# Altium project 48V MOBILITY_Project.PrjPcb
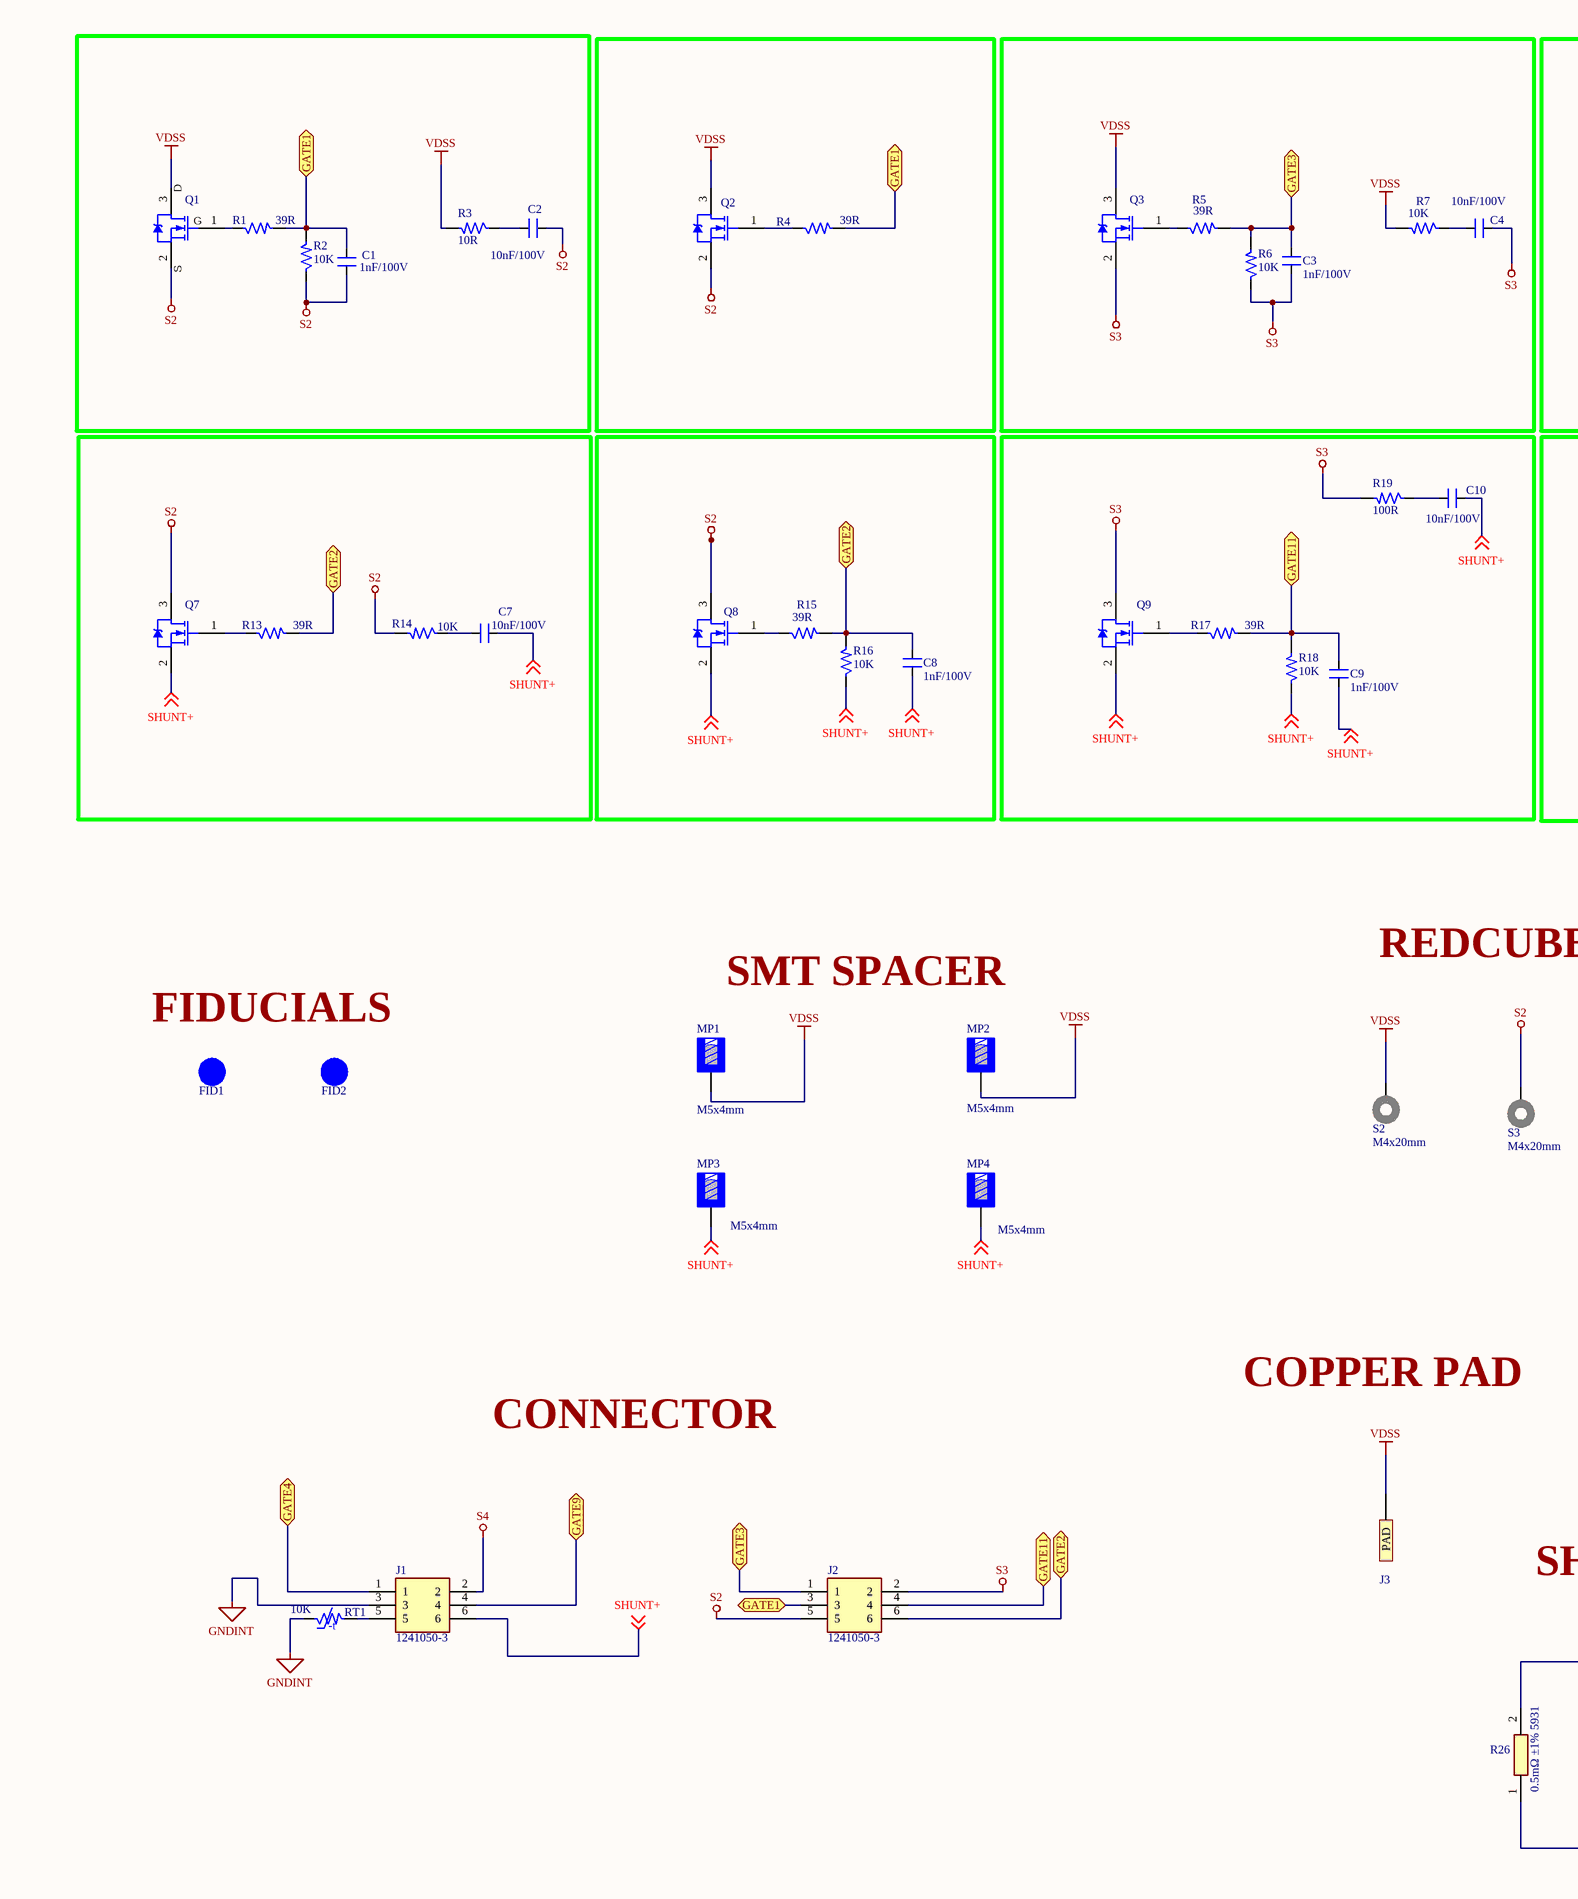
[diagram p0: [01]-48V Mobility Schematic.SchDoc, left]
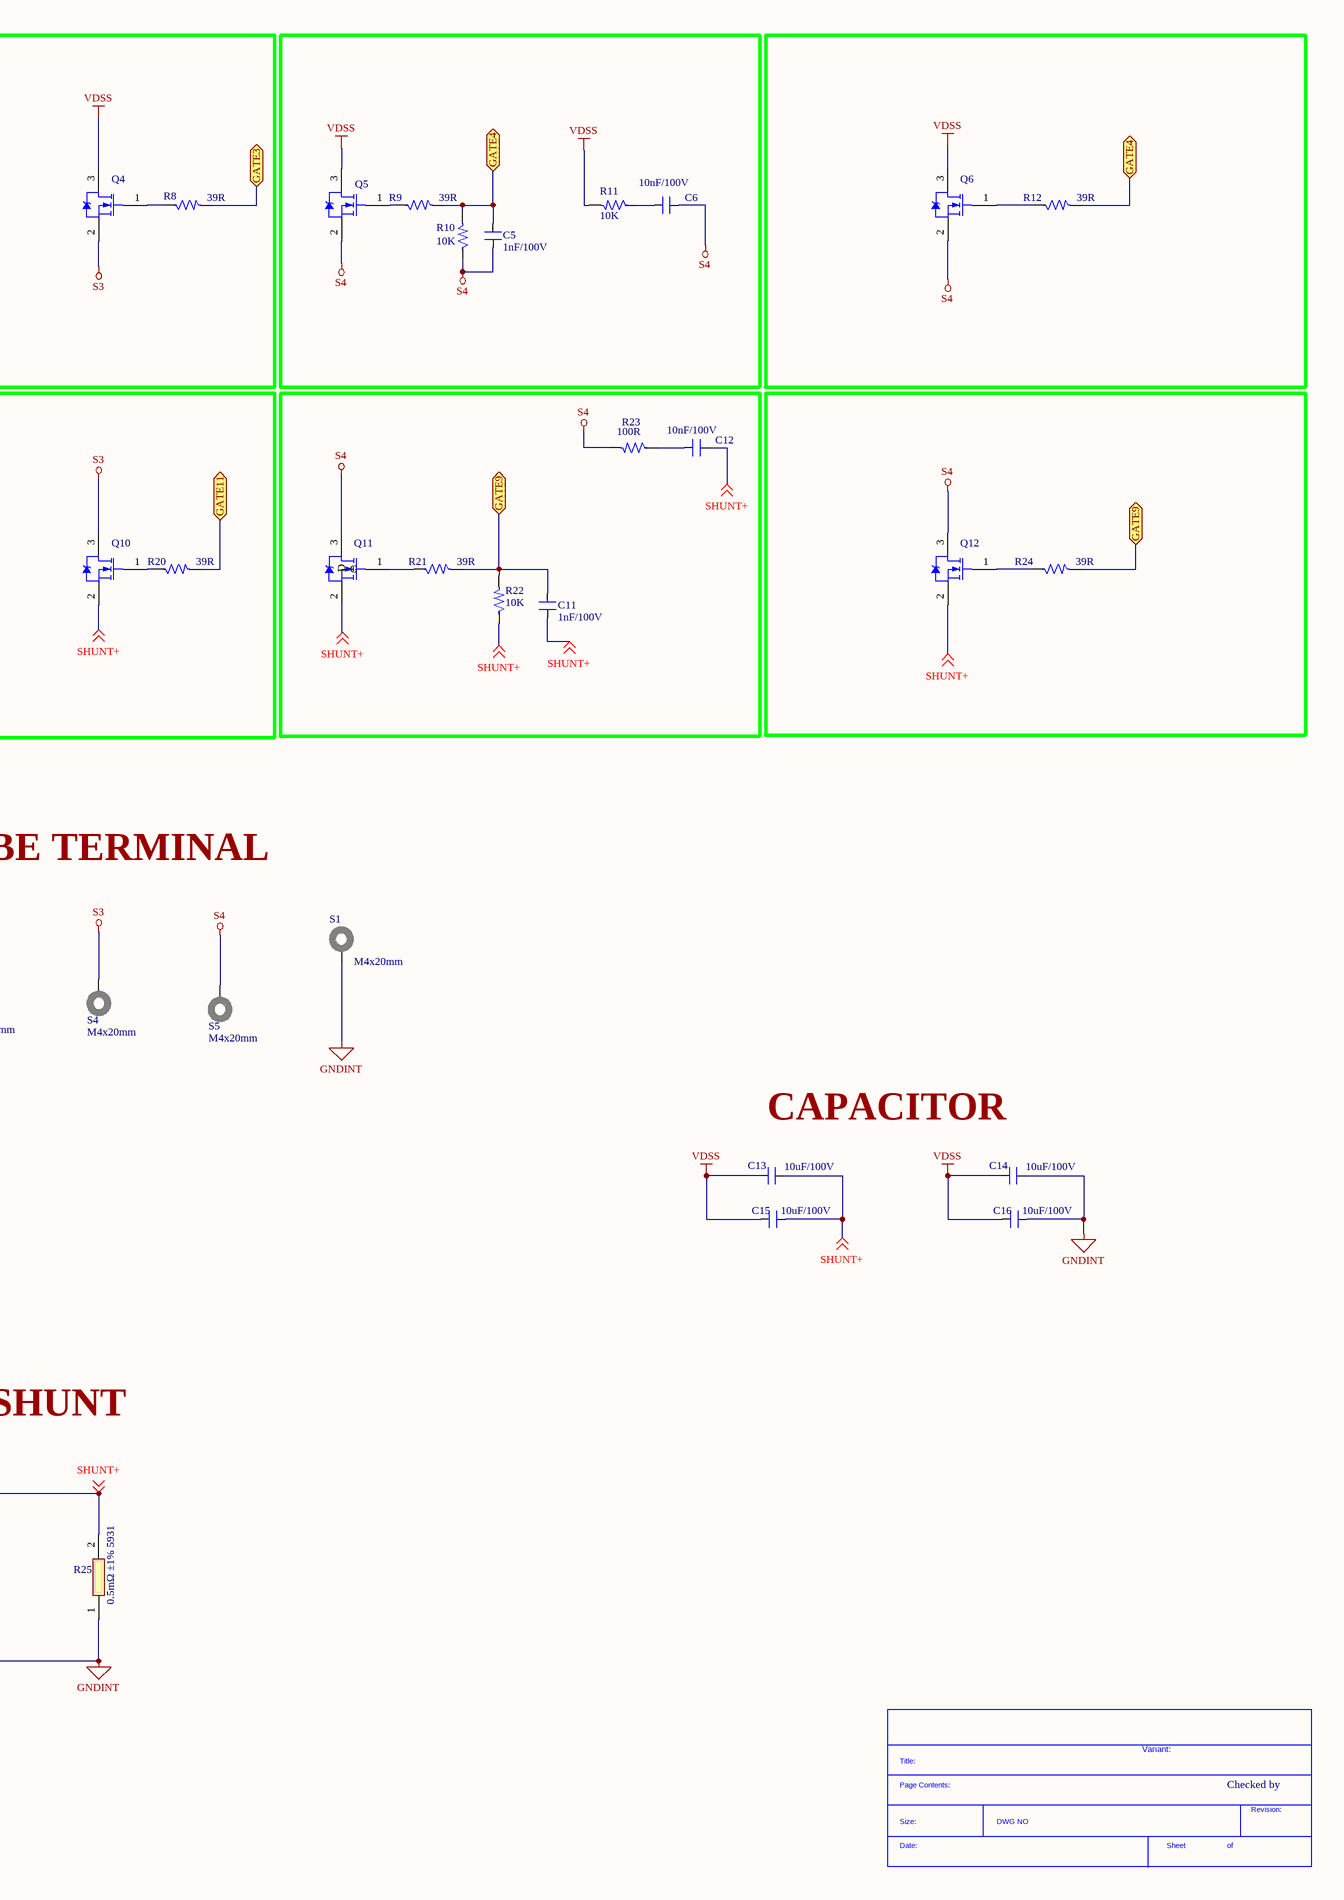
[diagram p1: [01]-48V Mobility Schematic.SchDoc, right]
1 sheet, 70 parts. Net scope: flat (ports and power ports of the same name join across sheets).
Board file: 48V MOBILITY.PcbDoc

## Sheet [01]-48V Mobility Schematic.SchDoc
size A2; DocumentNumber: 5; SheetNumber: 5; SheetTotal: 5; PageSetup: Record=PageOptions¦CenterHorizontal=True¦CenterVertical=True¦PrintScale=1.07¦XCorrection=1.00¦YCorrection=1.00¦PrintKind=1¦BorderSize=5000000¦LeftOffset=0¦BottomOffset=0¦Orientation=2¦PaperLength=1000¦PaperWidth=1000¦Scale=100¦PaperSource=7¦PrintQuality=600¦MediaType=1¦DitherType=10¦PaperKind=A3¦PrintScaleMode=1

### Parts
*?  SDTitleBlock  (value not drawn)  (graphical)
C1  1nF/100V  [CAP_0805]
C2  10nF/100V  [CAP_0805]
C3  1nF/100V  [CAP_0805]
C4  10nF/100V  [CAP_0805]
C5  1nF/100V  [CAP_0805]
C6  10nF/100V  [CAP_0805]
C7  10nF/100V  [CAP_0805]
C8  1nF/100V  [CAP_0805]
C9  1nF/100V  [CAP_0805]
C10  10nF/100V  [CAP_0805]
C11  1nF/100V  [MY_1206]
C12  10nF/100V  [MY_0603]
C13  10uF/100V  [CAP_1812]
C14  10uF/100V  [CAP_1812]
C15  10uF/100V  [CAP_1812]
C16  10uF/100V  [CAP_1812]
FID1  FID_1MM  [FID_40x20D]  (value not drawn)  (no BOM)
FID2  FID_1MM  [FID_40x20D]  (value not drawn)  (no BOM)
J1  1241050-3  [1241050-3]
J2  1241050-3  [1241050-3]
J3  78X157 PAD  [VDDS PAD]  (value not drawn)
MP1  M5x4mm  [POWER PAD]
MP2  M5x4mm  [POWER PAD]
MP3  M5x4mm  [POWER PAD]
MP4  M5x4mm  [POWER PAD]
Q1  HYG085N04LA1D  [D2PAK]  (value not drawn)
Q2  HYG085N04LA1D  [D2PAK]  (value not drawn)
Q3  HYG085N04LA1D  [D2PAK]  (value not drawn)
Q4  HYG085N04LA1D  [D2PAK]  (value not drawn)
Q5  HYG085N04LA1D  [D2PAK]  (value not drawn)
Q6  HYG085N04LA1D  [D2PAK]  (value not drawn)
Q7  HYG085N04LA1D  [D2PAK]  (value not drawn)
Q8  HYG085N04LA1D  [D2PAK]  (value not drawn)
Q9  HYG085N04LA1D  [D2PAK]  (value not drawn)
Q10  HYG085N04LA1D  [D2PAK]  (value not drawn)
Q11  HYG085N04LA1D  [D2PAK]  (value not drawn)
Q12  HYG085N04LA1D  [D2 PAK Q12]  (value not drawn)
R1  39R  [MY_0805]
R2  10K  [MY_0805]
R3  10R  [MY_1206]
R4  39R  [MY_0805]
R5  39R  [MY_0805]
R6  10K  [MY_0805]
R7  10K  [MY_1206]
R8  39R  [MY_0805]
R9  39R  [MY_0805]
R10  10K  [MY_0805]
R11  10K  [MY_1206]
R12  39R  [MY_0805]
R13  39R  [MY_0805]
R14  10K  [MY_1206]
R15  39R  [MY_0805]
R16  10K  [MY_0805]
R17  39R  [MY_0805]
R18  10K  [MY_0805]
R19  100R  [MY_1206]
R20  39R  [MY_0805]
R21  39R  [MY_0603]
R22  10K  [MY_1206]
R23  100R  [MY_1206]
R24  39R  [MY_0805]
R25  0.5mΩ ±1% 5931  [Current Sense Resistors_5931]
R26  0.5mΩ ±1% 5931  [Current Sense Resistors_5931]
RT1  10K  [RES_0805]
S1  M4x20mm  [15mm spacer]
S2  M4x20mm  [15mm spacer]
S3  M4x20mm  [15mm spacer]
S4  M4x20mm  [15mm spacer]
S5  M4x20mm  [15mm spacer]

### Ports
GATE1 (bidir), GATE2 (bidir), GATE3 (bidir), GATE4 (bidir), GATE9 (bidir), GATE11 (bidir)

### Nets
GNDINT: C14.1 C16.1 J1.3 R25.1 R26.1 RT1.1 S1.1
S2: C1.1 C2.2 J2.5 Q1.2(S) Q2.2(S) Q7.3(D) Q8.3(D) R2.1 R14.2 S3.1
S3: C3.1 C4.1 J2.2 Q3.2(S) Q4.2(S) Q9.3(D) Q10.3(D) R6.1 R19.2 S4.1
S4: C5.1 C6.1 J1.2 Q5.2(S) Q6.2(S) Q11.3(D) Q12.3(D) R10.1 R23.2 S5.1
VDSS: C13.2 C14.2 C15.2 C16.2 J3.1(PAD) MP1.1 MP2.1 Q1.3(D) Q2.3(D) Q3.3(D) Q4.3(D) Q5.3(D) Q6.3(D) R3.2 R7.2 R11.2 S2.1
SHUNT+: C7.1 C8.1 C9.1 C10.1 C11.1 C12.1 C13.1 C15.1 J1.6 MP3.1 MP4.1 Q7.2(S) Q8.2(S) Q9.2(S) Q10.2(S) Q11.2(S) Q12.2(S) R16.1 R18.1 R22.1 R25.2 R26.2 ; off-sheet SHUNT+
NetC1_2: C1.2 J2.3 R1.2 R2.2 R4.2 ; port GATE1
NetC2_1: C2.1 R3.1
NetC3_2: C3.2 J2.1 R5.2 R6.2 R8.2 ; port GATE3
NetC4_2: C4.2 R7.1
NetC5_2: C5.2 J1.1 R9.2 R10.2 R12.2 ; port GATE4
NetC6_2: C6.2 R11.1
NetC7_2: C7.2 R14.1
NetC8_2: C8.2 J2.6 R13.2 R15.2 R16.2 ; port GATE2
NetC9_2: C9.2 J2.4 R17.2 R18.2 R20.2 ; port GATE11
NetC10_2: C10.2 R19.1
NetC11_2: C11.2 J1.4 R21.2 R22.2 R24.2 ; port GATE9
NetC12_2: C12.2 R23.1
NetJ1_5: J1.5 RT1.2
NetQ1_1: Q1.1(G) R1.1
NetQ2_1: Q2.1(G) R4.1
NetQ3_1: Q3.1(G) R5.1
NetQ4_1: Q4.1(G) R8.1
NetQ5_1: Q5.1(G) R9.1
NetQ6_1: Q6.1(G) R12.1
NetQ7_1: Q7.1(G) R13.1
NetQ8_1: Q8.1(G) R15.1
NetQ9_1: Q9.1(G) R17.1
NetQ10_1: Q10.1(G) R20.1
NetQ11_1: Q11.1(G) R21.1
NetQ12_1: Q12.1(G) R24.1

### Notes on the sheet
- (near Q1) D
- (near Q1) G
- (near Q1) S
- SMT SPACER
- REDCUBE TERMINAL
- FIDUCIALS
- CAPACITOR
- COPPER PAD
- CONNECTOR
- SHUNT
- Variant:
- Checked by

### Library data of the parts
C1-C12 = CAP_33pF-50V-5%-0805: 33pF ±5% 50V Ceramic Capacitor C0G, NP0 0805 (2012 Metric); Manufacturer: Samsung; Manufacturer Part Number: CL21C330JBANNNC; Alternate Part Number-1: NA
C13-C16 = CAP_2.2uF-25V-10%-0805: 2.2µF ±10% 25V Ceramic Capacitor X7R 0805 (2012 Metric); Manufacturer: KEMET; Manufacturer Part Number: CL21B225KAFNFNE; Alternate Part Number-1: NA
FID1 FID2 = FID_1MM: Fiducial 40 mil Diameter and 120 mil Mask
J1 J2 = 1241050-3: Connector; Manufacturer_Name: TE Connectivity
J3 = SMD_PAD-78X157: SMD Pad of 2mm x 4mm 1 pin; Manufacturer: NA
MP1-MP4 = 7466105R: WP-SMBU SMT Internal blind-hole thread with pins, OD 9mm, M5x4mm, 70A; Manufacturer: Wurth Elektronik; Thread: M5; Surface: Tin; Thread Length: 4mm
Q1-Q12 = IRFRC20: HEXFET Power MOSFET; Note: Pin 2 is trimmed and is electrically connected to Drain.
R1 R4 R5 R8 R9 R12 R13 R15-R18 R20-R22 = RES_39R-3W-5%-TH: 39 Ohms ±5% 3W Through Hole Resistor Axial Flame Proof, Safety Wirewound; Manufacturer: Stackpole Electronics; Manufacturer Part Number: RWM041039R0JR15E1; Alternate Part Number-1: NA
R2 R6 R10 = RES_10K-0.1W-1%-0603: 10 kOhms ±1% 0.1W, 1/10W Chip Resistor 0603 (1608 Metric) Automotive AEC-Q200 Thick Film; Manufacturer: Walsin; Manufacturer Part Number: WR06X1002FTL; Alternate Part Number-1: 0603WAJ0103T5E
R3 R7 R11 R14 R19 R23 = RES_100R-0.1W-1%-0603: 100 Ohms ±1% 0.1W, 1/10W Chip Resistor 0603 (1608 Metric) Thick Film; Manufacturer: Walsin; Manufacturer Part Number: WR06X1000FTL; Alternate Part Number-1: MR06X1000FTL
R24 = RES_39R-3W-5%-TH: 390 Ohms ±5% 3W Through Hole Resistor Axial Flame Proof, Safety Wirewound; Manufacturer: Stackpole Electronics; Manufacturer Part Number: RWM041039R0JR15E1; Alternate Part Number-1: NA
R25 R26 = CR0603-JW-150ELF: Resistor; Manufacturer_Name: Bourns
RT1 = RT_10K-0805: NTC Thermistor 10k 0805 (2012 Metric); Manufacturer: Vishay BCcomponents; Manufacturer Part Number: NCP21XV103J03RA; Alternate Part Number-1: NA
S1-S5 = 9774010482: WA-SMSI SMT Steel Spacer, internal Thread, OD 8.2mm, M4x1mm; Manufacturer: Wurth Elektronik; Inner Diameter: 5.2mm; Surface: Tin; Thread: M4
